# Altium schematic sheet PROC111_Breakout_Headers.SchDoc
size 431 x 279 mm; Date: Not shown in title block; ApprovedBy: Not shown in title block; CheckedBy: Not shown in title block; Author: Not shown in title block; CompanyName: Not shown in title block; Engineer: Not shown in title block; Organization: Not shown in title block; Address1: Not shown in title block; Address2: Not shown in title block; Address3: Not shown in title block; Address4: Not shown in title block; DocumentNumber: 20; Revision: Use project parameter SCH_Rev; SheetNumber: 20; SheetTotal: 24; PageSetup: Record=PageOptions¦CenterHorizontal=True¦CenterVertical=True¦PrintScale=1.00¦XCorrection=1.00¦YCorrection=1.00¦PrintKind=0¦BorderSize=5000000¦LeftOffset=0¦BottomOffset=0¦Orientation=2¦PaperLength=1000¦PaperWidth=1000¦Scale=100¦PaperSource=15¦PrintQuality=600¦MediaType=1¦DitherType=10¦PaperKind=Letter¦PrintScaleMode=1
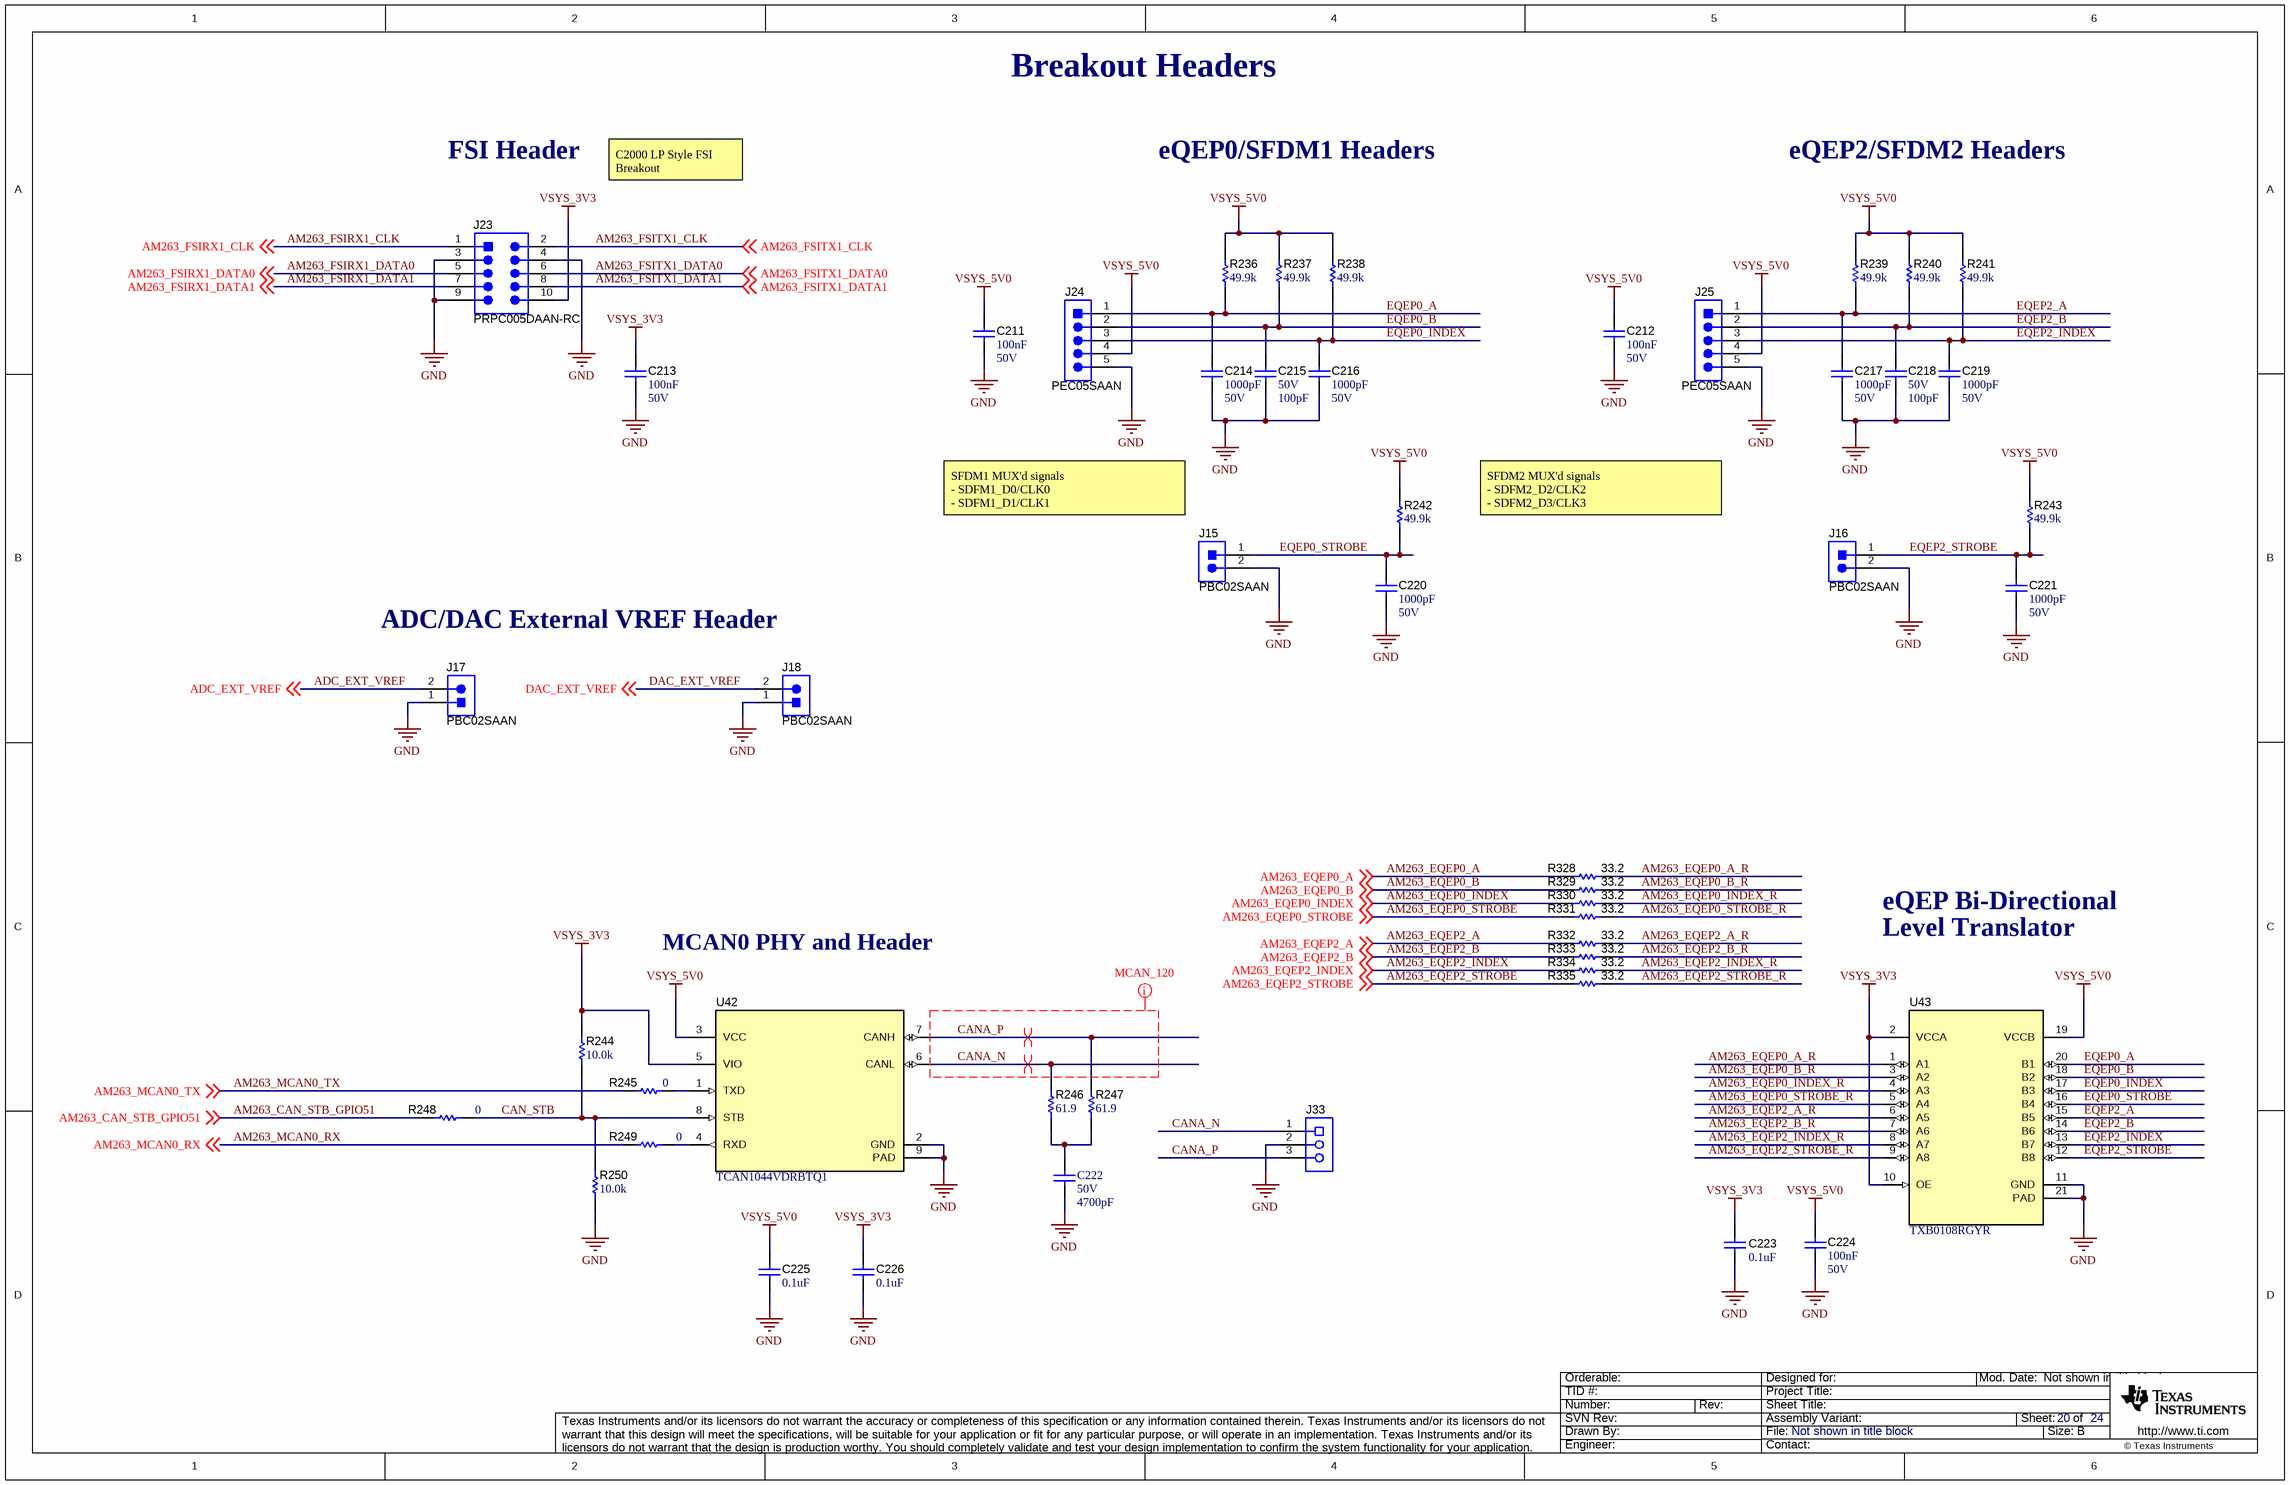
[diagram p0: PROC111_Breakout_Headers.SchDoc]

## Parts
C211  Cap_F: 100nF  VDC_V: 50V  [0603]  (hidden comment: GCM188R71H104KA57D)
C212  Cap_F: 100nF  VDC_V: 50V  [0603]  (hidden comment: GCM188R71H104KA57D)
C213  Cap_F: 100nF  VDC_V: 50V  [0603]  (hidden comment: GCM188R71H104KA57D)
C214  ValueDisplayed: 1000pF  VDC_V: 50V  [0603]  (hidden comment: GCM1885C1H102JA16D)
C215  VDC_V: 50V  ValueDisplayed: 100pF  [0603]  (hidden comment: GRM1885C1H101JA01D)
C216  ValueDisplayed: 1000pF  VDC_V: 50V  [0603]  (hidden comment: GCM1885C1H102JA16D)
C217  ValueDisplayed: 1000pF  VDC_V: 50V  [0603]  (hidden comment: GCM1885C1H102JA16D)
C218  VDC_V: 50V  ValueDisplayed: 100pF  [0603]  (hidden comment: GRM1885C1H101JA01D)
C219  ValueDisplayed: 1000pF  VDC_V: 50V  [0603]  (hidden comment: GCM1885C1H102JA16D)
C220  ValueDisplayed: 1000pF  VDC_V: 50V  [0603]  (hidden comment: GCM1885C1H102JA16D)
C221  ValueDisplayed: 1000pF  VDC_V: 50V  [0603]  (hidden comment: GCM1885C1H102JA16D)
C222  VDC_V: 50V  ValueDisplayed: 4700pF  [0402]  (hidden comment: GCM155R71H472KA37D)
C223  ValueDisplayed: 0.1uF  [0402]  (hidden comment: GRM155R71E104KE14D)
C224  Cap_F: 100nF  VDC_V: 50V  [0603]  (hidden comment: GCM188R71H104KA57D)
C225  ValueDisplayed: 0.1uF  [0402]  (hidden comment: GRM155R71E104KE14D)
C226  ValueDisplayed: 0.1uF  [0402]  (hidden comment: GRM155R71E104KE14D)
J15  PBC02SAAN  [Sullins_PBC02SAAN]
J16  PBC02SAAN  [Sullins_PBC02SAAN]
J17  PBC02SAAN  [Sullins_PBC02SAAN]
J18  PBC02SAAN  [Sullins_PBC02SAAN]
J23  PRPC005DAAN-RC  [Sullins_xxPC005DAAN-RC]
J24  PEC05SAAN  [Sullins_PxC05SAAN]
J25  PEC05SAAN  [Sullins_PxC05SAAN]
J33  OSTTE030161  [On-Shore_OSTTE030161]  (value not drawn)
R236  ValueDisplayed: 49.9k  [0402]  (hidden comment: ERJ-2RKF4992X)
R237  ValueDisplayed: 49.9k  [0402]  (hidden comment: ERJ-2RKF4992X)
R238  ValueDisplayed: 49.9k  [0402]  (hidden comment: ERJ-2RKF4992X)
R239  ValueDisplayed: 49.9k  [0402]  (hidden comment: ERJ-2RKF4992X)
R240  ValueDisplayed: 49.9k  [0402]  (hidden comment: ERJ-2RKF4992X)
R241  ValueDisplayed: 49.9k  [0402]  (hidden comment: ERJ-2RKF4992X)
R242  ValueDisplayed: 49.9k  [0402]  (hidden comment: ERJ-2RKF4992X)
R243  ValueDisplayed: 49.9k  [0402]  (hidden comment: ERJ-2RKF4992X)
R244  ValueDisplayed: 10.0k  [0402L]  (hidden comment: CRCW040210K0FKED)
R245  value 0  [0402L]  (hidden comment: ERJ-2GE0R00X)
R246  ValueDisplayed: 61.9  [0402L]  (hidden comment: CRCW040261R9FKED)
R247  ValueDisplayed: 61.9  [0402L]  (hidden comment: CRCW040261R9FKED)
R248  ValueDisplayed: 0  [0402L]  (hidden comment: ERJ-2GE0R00X)
R249  ValueDisplayed: 0  [0402L]  (hidden comment: ERJ-2GE0R00X)
R250  ValueDisplayed: 10.0k  [0402L]  (hidden comment: CRCW040210K0FKED)
R328  ValueDisplayed: 33.2  [0402]  (hidden comment: CRCW040233R2FKED)
R329  ValueDisplayed: 33.2  [0402]  (hidden comment: CRCW040233R2FKED)
R330  ValueDisplayed: 33.2  [0402]  (hidden comment: CRCW040233R2FKED)
R331  ValueDisplayed: 33.2  [0402]  (hidden comment: CRCW040233R2FKED)
R332  ValueDisplayed: 33.2  [0402]  (hidden comment: CRCW040233R2FKED)
R333  ValueDisplayed: 33.2  [0402]  (hidden comment: CRCW040233R2FKED)
R334  ValueDisplayed: 33.2  [0402]  (hidden comment: CRCW040233R2FKED)
R335  ValueDisplayed: 33.2  [0402]  (hidden comment: CRCW040233R2FKED)
U42  TCAN1044VDRBTQ1  [DRB0008J]
U43  TXB0108RGYR  [RGY0020A]

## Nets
GND: C211.2 C212.2 C213.2 C214.2 C215.2 C216.2 C217.2 C218.2 C219.2 C220.2 C221.2 C222.2 C223.1 C224.2 C225.1 C226.1 J15.2 J16.2 J17.1 J18.1 J23.3 J23.4 J23.9 J24.5 J25.5 J33.2 R250.1 U42.2(GND) U42.9(PAD) U43.11(GND) U43.21(PAD)
VSYS_3V3: C213.1 C223.2 C226.2 J23.10 R244.2 U42.5(VIO) U43.2(VCCA) U43.10(OE)
VSYS_5V0: C211.1 C212.1 C224.1 C225.2 J24.4 J25.4 R236.2 R237.2 R238.2 R239.2 R240.2 R241.2 R242.2 R243.2 U42.3(VCC) U43.19(VCCB)
ADC_EXT_VREF: J17.2 ; off-sheet ADC_EXT_VREF
AM263_CAN_STB_GPIO51: R248.2 ; off-sheet AM263_CAN_STB_GPIO51
AM263_EQEP0_A: R328.1 ; off-sheet AM263_EQEP0_A
AM263_EQEP0_A_R: R328.2 U43.1(A1)
AM263_EQEP0_B: R329.1 ; off-sheet AM263_EQEP0_B
AM263_EQEP0_B_R: R329.2 U43.3(A2)
AM263_EQEP0_INDEX: R330.1 ; off-sheet AM263_EQEP0_INDEX
AM263_EQEP0_INDEX_R: R330.2 U43.4(A3)
AM263_EQEP0_STROBE: R331.1 ; off-sheet AM263_EQEP0_STROBE
AM263_EQEP0_STROBE_R: R331.2 U43.5(A4)
AM263_EQEP2_A: R332.1 ; off-sheet AM263_EQEP2_A
AM263_EQEP2_A_R: R332.2 U43.6(A5)
AM263_EQEP2_B: R333.1 ; off-sheet AM263_EQEP2_B
AM263_EQEP2_B_R: R333.2 U43.7(A6)
AM263_EQEP2_INDEX: R334.1 ; off-sheet AM263_EQEP2_INDEX
AM263_EQEP2_INDEX_R: R334.2 U43.8(A7)
AM263_EQEP2_STROBE: R335.1 ; off-sheet AM263_EQEP2_STROBE
AM263_EQEP2_STROBE_R: R335.2 U43.9(A8)
AM263_FSIRX1_CLK: J23.1 ; off-sheet AM263_FSIRX1_CLK
AM263_FSIRX1_DATA0: J23.5 ; off-sheet AM263_FSIRX1_DATA0
AM263_FSIRX1_DATA1: J23.7 ; off-sheet AM263_FSIRX1_DATA1
AM263_FSITX1_CLK: J23.2 ; off-sheet AM263_FSITX1_CLK
AM263_FSITX1_DATA0: J23.6 ; off-sheet AM263_FSITX1_DATA0
AM263_FSITX1_DATA1: J23.8 ; off-sheet AM263_FSITX1_DATA1
AM263_MCAN0_RX: R249.1 ; off-sheet AM263_MCAN0_RX
AM263_MCAN0_TX: R245.1 ; off-sheet AM263_MCAN0_TX
CAN_STB: R244.1 R248.1 R250.2 U42.8(STB)
CANA_N: J33.1 R246.2 U42.6(CANL)
CANA_P: J33.3 R247.2 U42.7(CANH)
DAC_EXT_VREF: J18.2 ; off-sheet DAC_EXT_VREF
EQEP0_A: C214.1 J24.1 R236.1 U43.20(B1)
EQEP0_B: C215.1 J24.2 R237.1 U43.18(B2)
EQEP0_INDEX: C216.1 J24.3 R238.1 U43.17(B3)
EQEP0_STROBE: C220.1 J15.1 R242.1 U43.16(B4)
EQEP2_A: C217.1 J25.1 R239.1 U43.15(B5)
EQEP2_B: C218.1 J25.2 R240.1 U43.14(B6)
EQEP2_INDEX: C219.1 J25.3 R241.1 U43.13(B7)
EQEP2_STROBE: C221.1 J16.1 R243.1 U43.12(B8)
NetC222_1: C222.1 R246.1 R247.1
NetR245_2: R245.2 U42.1(TXD)
NetR249_2: R249.2 U42.4(RXD)

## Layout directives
differential pair: CANA_N, CANA_P
mark named MCAN_120: CANA_N, CANA_P

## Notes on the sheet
- Breakout Headers
- FSI Header
- eQEP0/SFDM1 Headers
- eQEP2/SFDM2 Headers
- C2000 LP Style FSI Breakout
- SFDM1 MUX'd signals
  - SDFM1_D0/CLK0
  - SDFM1_D1/CLK1
- SFDM2 MUX'd signals
  - SDFM2_D2/CLK2
  - SDFM2_D3/CLK3
- ADC/DAC External VREF Header
- MCAN0 PHY and Header
- eQEP Bi-Directional
- Level Translator

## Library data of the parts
C211-C213 C224 = CMP-0007144-4: CAP, CERM, 0.1 uF, 50 V, +/- 10%, X7R, 0603; Manufacturer: MuRata; TaMin_C: -55°C; ESR_ohm: 20m; Polarized: N; SizeAreaWB_mm2: 4.68; Value1: 0.02 ohm; U/M: EA; Value: 0.1uF; TaMax_C: 125°C; SizeZ_mm: 1; SizeX_mm: 1.6; SizeY_mm: 0.8; SizeArea_mm2: 1.28; IRMS_A: 1.84A; AEC Category: Q200
C214 C216 C217 C219-C221 = CMP-0086079-1: CAP, CERM, 1000 pF, 50 V,+/- 5%, C0G/NP0, AEC-Q200 Grade 1, 0603; Manufacturer: MuRata; Value: 1000pF; U/M: EA; Green_Lifecycle: Active; SizeAreaWB_mm2: 4.68; SizeX_mm: 1.6; SizeZ_mm: 1; AEC Qualified: Y; SizeArea_mm2: 1.28; TaMax_C: 125°C; SizeY_mm: 0.8; Cap_F: 1nF; TaMin_C: -55°C; Green_REACh: Incomplete; AEC Category: Q200; Polarized: N
C215 C218 = CMP-0007171-4: CAP, CERM, 100 pF, 50 V, +/- 5%, C0G/NP0, 0603; Manufacturer: MuRata; TaMin_C: -55°C; Polarized: N; SizeAreaWB_mm2: 4.68; Value1: Unknown; U/M: EA; Value: 100pF; TaMax_C: 125°C; SizeZ_mm: 1; SizeX_mm: 1.6; SizeY_mm: 0.8; SizeArea_mm2: 1.28; AEC Category: Q200
C222 = CMP-0006361-2: CAP, CERM, 4700 pF, 50 V, +/- 10%, X7R, AEC-Q200 Grade 1, 0402; Manufacturer: MuRata; TaMin_C: -55°C; Polarized: N; SizeAreaWB_mm2: 3; Value1: Unknown; U/M: EA; Value: 4700pF; TaMax_C: 125°C; SizeZ_mm: 0.6; SizeX_mm: 1; SizeY_mm: 0.5; AEC Qualified: Y; Cap_F: 4.7nF; AEC Category: Q200
C223 C225 C226 = CMP-0006659-2: CAP, CERM, 0.1 uF, 25 V, +/- 10%, X7R, 0402; Manufacturer: MuRata; TaMin_C: -55°C; Polarized: N; SizeAreaWB_mm2: 3; U/M: EA; Value: 0.1uF; TaMax_C: 125°C; SizeZ_mm: 0.6; SizeX_mm: 1; SizeY_mm: 0.5; Value2: 25V; Cap_F: 100nF; AEC Category: Q200; Value1: Unknown
J15-J18 = CMP-0054566-1: Header, 100mil, 2x1, Gold, TH; Manufacturer: Sullins Connector Solutions; CNHeader: TRUE; Current_A: 3A; Green_Lifecycle: Active; Shrouded: N; Gender: Male; Green_REACh: Passed; Voltage_V: 1.8kV; Row_Count: 1; Pitch_mm: 2.54; CT: FALSE; Cert_UL: Y
J23 = CMP-0080722-2: Header, 2.54mm, 5x2, Gold, TH; Manufacturer: Sullins Connector Solutions; Pitch_mm: 2.54; Gender: Male; Cert_UL: Y; Current_A: 3A; Voltage_V: 1kV; Shrouded: N; Row_Count: 2
J24 J25 = CMP-0054597-1: Header, 2.54mm, 5x1, Tin, TH; Manufacturer: Sullins Connector Solutions; CNHeader: TRUE; Current_A: 3A; Green_Lifecycle: Not Set; Shrouded: N; Gender: Male; Green_REACh: Incomplete; Voltage_V: 1.8kV; Row_Count: 1; Pitch_mm: 2.54; CT: FALSE; Cert_UL: Y
J33 = CMP-0075352-1: Terminal Block, 3.5mm, 3x1, Tin, R/A, TH; Manufacturer: On-Shore Technology; CNHeader: False; Current_A: 10A; Green_Lifecycle: Not Set; Gender: Female; Cert_CSA: Y; Green_REACh: Incomplete; Voltage_V: 125V; Row_Count: 1; Pitch_mm: 3.5; CT: True
R236-R243 = CMP-0026702-1: RES, 49.9 k, 1%, 0.1 W, AEC-Q200 Grade 0, 0402; Manufacturer: Panasonic; Power_W: 100mW; TempCo: 100 ppm/C; Value_Code: 49k9; U/M: EA; Value: 49.9k; EIA_Code: E96; SizeX_mm: 1; SizeY_mm: 0.5; SizeZ_mm: 0.6; Value2: 0.1W; AEC Qualified: Y; VDC_V: 50V; AEC Grade: 0; AEC Category: Q200
R244 R250 = CMP-0025958-3: RES, 10.0 k, 1%, 0.063 W, AEC-Q200 Grade 0, 0402; Manufacturer: Vishay-Dale; Power_W: 63mW; TempCo: 100 ppm/C; Value_Code: 10k0; Value: 10.0k; EIA_Code: E96; Res_ohm: 10k; SizeX_mm: 1; SizeY_mm: 0.5; SizeZ_mm: 0.6; Value2: 0.063W; AEC Qualified: Y; VDC_V: 50V; AEC Category: Q200; AEC Grade: 0
R245 = CMP-0026992-3: RES, 0, 5%, 0.1 W, AEC-Q200 Grade 0, 0402; Manufacturer: Panasonic; Power_W: 100mW; TempCo: 600 ppm/C; Value_Code: 0000; EIA_Code: E24; SizeX_mm: 1; SizeY_mm: 0.5; SizeZ_mm: 0.6; Value2: 0.1W; AEC Qualified: Y; VDC_V: 50V; AEC Category: Q200; SizeAreaWB_mm2: 3
R246 R247 = CMP-0026491-2: RES, 61.9, 1%, 0.063 W, AEC-Q200 Grade 0, 0402; Manufacturer: Vishay-Dale; Power_W: 63mW; TempCo: 100 ppm/C; Value_Code: 61R9; Value: 61.9; EIA_Code: E96; SizeX_mm: 1; SizeY_mm: 0.5; SizeZ_mm: 0.6; Value2: 0.063W; AEC Qualified: Y; VDC_V: 50V; AEC Category: Q200; AEC Grade: 0
R248 R249 = CMP-0026992-3: RES, 0, 5%, 0.1 W, AEC-Q200 Grade 0, 0402; Manufacturer: Panasonic; Power_W: 100mW; TempCo: 600 ppm/C; Value_Code: 0000; Value: 0; EIA_Code: E24; SizeX_mm: 1; SizeY_mm: 0.5; SizeZ_mm: 0.6; Value2: 0.1W; AEC Qualified: Y; VDC_V: 50V; AEC Category: Q200; SizeAreaWB_mm2: 3
R328-R335 = CMP-0026299-2: RES, 33.2, 1%, 0.063 W, AEC-Q200 Grade 0, 0402; Manufacturer: Vishay-Dale; Power_W: 63mW; TempCo: 100 ppm/C; Value_Code: 33R2; Value: 33.2; EIA_Code: E96; SizeX_mm: 1; SizeY_mm: 0.5; SizeZ_mm: 0.6; Value2: 0.063W; AEC Qualified: Y; VDC_V: 50V; AEC Category: Q200; AEC Grade: 0
U42 = CMP-0079884-2: Automotive High Speed CAN Transceiver, DRB0008J (VSON-8); Alternate Manufacturer: Texas Instruments; Alternate PartNumber: TCAN1044VDRBRQ1; SizeX_mm: 3; AEC Category: Q200; SizeAreaWB_mm2: 16; SizeZ_mm: 1; SizeArea_mm2: 9; AEC Qualified: Y; CompType: IC
U43 = CMP-0074359-2: 8-Bit Bidirectional Voltage-Level Shifter with Auto Direction Sensing and +/-15-kV ESD Protect, RGY0020A (VQFN-20); Manufacturer: Texas Instruments; SizeZ_mm: 1.0; SizeX_mm: 3.5; SizeY_mm: 4.5; SizeArea_mm2: 15.75; CompType: IC; U/M: EA; SizeAreaWB_mm2: 24.75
